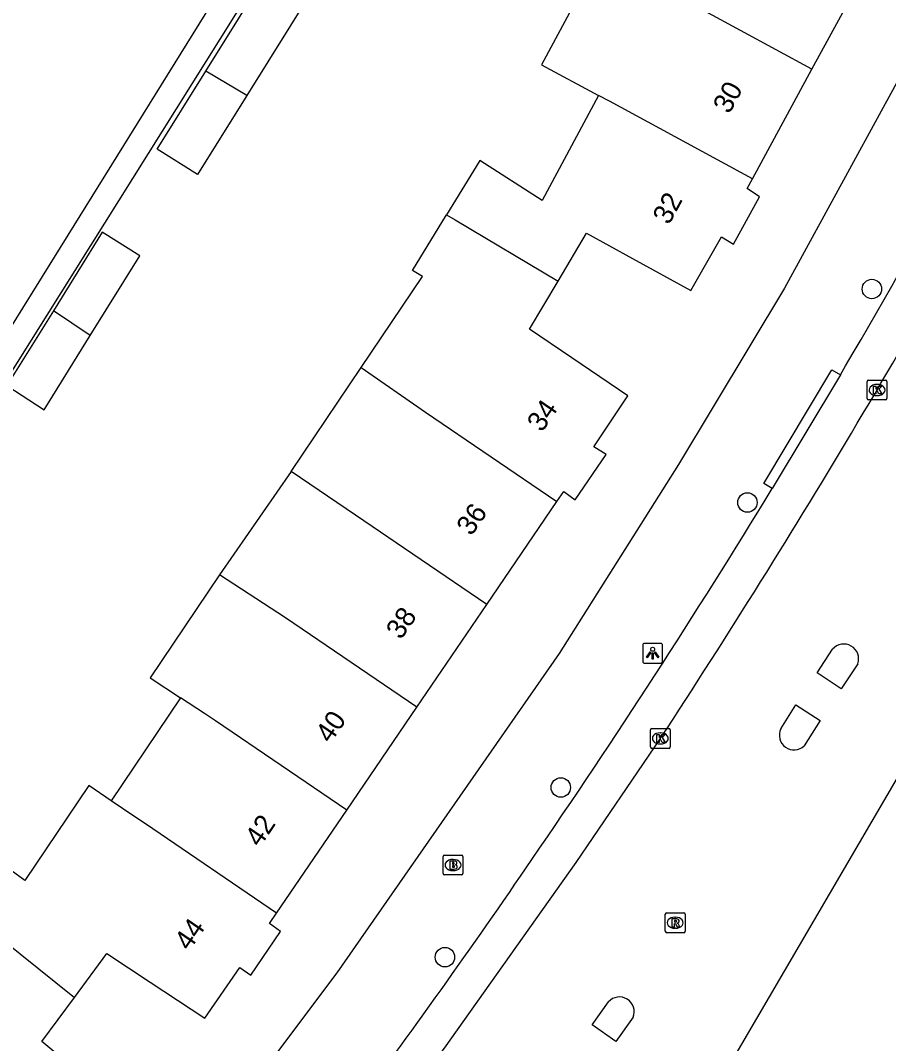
# Model space of a CAD drawing. Extents: x 161771 to 163125, y 382479 to 383177.
# Drawn here: x 162405.3 to 162448.9, y 382626.5 to 382677.9 of the extents above; entities that cross this region are included whole.
import ezdxf

# ---------------------------------------------------------------- set-up
doc = ezdxf.new("R2010")
doc.units = 0
for name, color, linetype in [('IMGEO_Boom', 7, 'Continuous'), ('IMGEO_Brandkraan', 7, 'Continuous'), ('IMGEO_Kolk', 7, 'Continuous'), ('IMGEO_Lichtpunt', 7, 'Continuous'), ('IMGEO_Pand', 7, 'Continuous'), ('IMGEO_Pand_nummerreeks', 7, 'Continuous'), ('IMGEO_Rijbaan_lokaal_open', 7, 'Continuous'), ('IMGEO_Rioolput', 7, 'Continuous'), ('IMGEO_Voetpad_open', 7, 'Continuous')]:
    doc.layers.add(name, color=color, linetype=linetype)

msp = doc.modelspace()

# ---------------------------------------------------------------- linework, layer by layer
at = {"layer": 'IMGEO_Boom'}
for centre in [(162448.106, 382664.408), (162441.847, 382653.678), (162432.46, 382639.354), (162426.633, 382630.828)]:
    msp.add_circle(centre, 0.489, dxfattribs=at)
at = {"layer": 'IMGEO_Brandkraan'}
for p, q in [((162426.539, 382635.032), (162426.539, 382635.884)), ((162426.614, 382635.958), (162427.466, 382635.958)), ((162427.027, 382635.738), (162427.052, 382635.738)), ((162427.54, 382635.884), (162427.54, 382635.032)), ((162427.05, 382635.178), (162427.025, 382635.178)), ((162427.466, 382634.958), (162426.614, 382634.958))]:
    msp.add_line(p, q, dxfattribs=at)
for points in [[(162426.539, 382635.032), (162426.539, 382635.884)], [(162426.614, 382635.958), (162427.466, 382635.958)], [(162426.887, 382635.658), (162426.887, 382635.258), (162427.1, 382635.258)], [(162427.118, 382635.658), (162426.887, 382635.658)], [(162427.066, 382635.577), (162427.012, 382635.577), (162427.012, 382635.501)], [(162427.54, 382635.884), (162427.54, 382635.032)], [(162427.012, 382635.501), (162427.065, 382635.501)], [(162427.074, 382635.425), (162427.012, 382635.425), (162427.012, 382635.344)], [(162427.012, 382635.344), (162427.074, 382635.344)], [(162427.466, 382634.958), (162426.614, 382634.958)]]:
    msp.add_lwpolyline(points, dxfattribs=at)
for centre, radius, start, end in [((162426.616, 382635.882), 0.0765, 91.552, 178.448), ((162426.616, 382635.882), 0.0765, 91.552, 178.448), ((162427.067, 382635.539), 0.0379, 267.8285, 90.9355), ((162427.122, 382635.513), 0.145, 59.4692, 91.5367), ((162427.147, 382635.56), 0.0922, 285.5137, 58.1501), ((162427.464, 382635.882), 0.0765, 1.552, 88.448), ((162427.464, 382635.882), 0.0765, 1.552, 88.448), ((162426.616, 382635.034), 0.0765, 181.552, 268.448), ((162426.616, 382635.034), 0.0765, 181.552, 268.448), ((162427.075, 382635.384), 0.0404, 269.8759, 90.5077), ((162427.106, 382635.509), 0.251, 268.6676, 293.5347), ((162427.152, 382635.368), 0.105, 301.3115, 78.989), ((162427.464, 382635.034), 0.0765, 271.552, 358.448), ((162427.464, 382635.034), 0.0765, 271.552, 358.448)]:
    msp.add_arc(centre, radius, start, end, dxfattribs=at)
for centre, major_axis, ratio, start_param, end_param in [((162427.026, 382635.458), (-0.387, 0.002), 0.722429, 4.712389, 7.853982), ((162427.051, 382635.458), (-0.39, 0.002), 0.717154, 1.570796, 4.712389)]:
    msp.add_ellipse(centre, major_axis=major_axis, ratio=ratio, start_param=start_param, end_param=end_param, dxfattribs=at)
at = {"layer": 'IMGEO_Kolk'}
for p, q in [((162447.865, 382658.908), (162447.865, 382659.76)), ((162447.94, 382659.834), (162448.792, 382659.834)), ((162448.866, 382659.76), (162448.866, 382658.908)), ((162448.353, 382659.614), (162448.378, 382659.614)), ((162448.792, 382658.834), (162447.94, 382658.834)), ((162448.376, 382659.054), (162448.351, 382659.054)), ((162436.966, 382641.395), (162436.966, 382642.247)), ((162437.041, 382642.321), (162437.893, 382642.321)), ((162437.967, 382642.247), (162437.967, 382641.395)), ((162437.454, 382642.101), (162437.479, 382642.101)), ((162437.893, 382641.321), (162437.041, 382641.321)), ((162437.477, 382641.541), (162437.452, 382641.541))]:
    msp.add_line(p, q, dxfattribs=at)
for points in [[(162447.865, 382658.908), (162447.865, 382659.76)], [(162447.94, 382659.834), (162448.792, 382659.834)], [(162448.866, 382659.76), (162448.866, 382658.908)], [(162448.186, 382659.534), (162448.309, 382659.534), (162448.309, 382659.383), (162448.439, 382659.534), (162448.603, 382659.534), (162448.457, 382659.383), (162448.61, 382659.134), (162448.458, 382659.134), (162448.373, 382659.298), (162448.309, 382659.231), (162448.309, 382659.134), (162448.186, 382659.134), (162448.186, 382659.534)], [(162448.792, 382658.834), (162447.94, 382658.834)], [(162436.966, 382641.395), (162436.966, 382642.247)], [(162437.041, 382642.321), (162437.893, 382642.321)], [(162437.967, 382642.247), (162437.967, 382641.395)], [(162437.287, 382642.021), (162437.41, 382642.021), (162437.41, 382641.87), (162437.54, 382642.021), (162437.704, 382642.021), (162437.558, 382641.87), (162437.711, 382641.621), (162437.559, 382641.621), (162437.474, 382641.785), (162437.41, 382641.718), (162437.41, 382641.621), (162437.287, 382641.621), (162437.287, 382642.021)], [(162437.893, 382641.321), (162437.041, 382641.321)]]:
    msp.add_lwpolyline(points, dxfattribs=at)
for centre, start, end in [((162447.942, 382659.758), 91.552, 178.448), ((162447.942, 382659.758), 91.552, 178.448), ((162448.79, 382659.758), 1.552, 88.448), ((162448.79, 382659.758), 1.552, 88.448), ((162447.942, 382658.91), 181.552, 268.448), ((162447.942, 382658.91), 181.552, 268.448), ((162448.79, 382658.91), 271.552, 358.448), ((162448.79, 382658.91), 271.552, 358.448), ((162437.043, 382642.245), 91.552, 178.448), ((162437.043, 382642.245), 91.552, 178.448), ((162437.891, 382642.245), 1.552, 88.448), ((162437.891, 382642.245), 1.552, 88.448), ((162437.043, 382641.397), 181.552, 268.448), ((162437.043, 382641.397), 181.552, 268.448), ((162437.891, 382641.397), 271.552, 358.448), ((162437.891, 382641.397), 271.552, 358.448)]:
    msp.add_arc(centre, 0.0765, start, end, dxfattribs=at)
for centre, major_axis, ratio, start_param, end_param in [((162448.352, 382659.334), (-0.387, 0.002), 0.722429, 4.712389, 7.853982), ((162448.377, 382659.334), (-0.39, 0.002), 0.717154, 1.570796, 4.712389), ((162437.453, 382641.821), (-0.387, 0.002), 0.722429, 4.712389, 7.853982), ((162437.478, 382641.821), (-0.39, 0.002), 0.717154, 1.570796, 4.712389)]:
    msp.add_ellipse(centre, major_axis=major_axis, ratio=ratio, start_param=start_param, end_param=end_param, dxfattribs=at)
at = {"layer": 'IMGEO_Lichtpunt'}
for p, q in [((162436.581, 382646.504), (162436.581, 382645.697)), ((162436.581, 382646.504), (162436.581, 382645.697)), ((162437.483, 382646.599), (162436.675, 382646.599)), ((162437.483, 382646.599), (162436.675, 382646.599)), ((162437.577, 382645.697), (162437.577, 382646.504)), ((162437.577, 382645.697), (162437.577, 382646.504)), ((162436.675, 382645.603), (162437.483, 382645.603)), ((162436.675, 382645.603), (162437.483, 382645.603))]:
    msp.add_line(p, q, dxfattribs=at)
for points in [[(162436.955, 382646.168), (162436.994, 382646.14), (162436.806, 382645.878), (162436.768, 382645.905), (162436.955, 382646.168)], [(162437.057, 382646.12), (162437.104, 382646.12), (162437.104, 382645.798), (162437.057, 382645.798), (162437.057, 382646.12)], [(162437.167, 382646.14), (162437.205, 382646.167), (162437.392, 382645.905), (162437.353, 382645.877), (162437.167, 382646.14)]]:
    msp.add_lwpolyline(points, dxfattribs=at)
msp.add_circle((162437.08, 382646.302), 0.0994, dxfattribs=at)
for centre, start, end in [((162436.675, 382646.504), 90, 180), ((162436.675, 382646.504), 90, 180), ((162437.483, 382646.504), 0, 90), ((162437.483, 382646.504), 0, 90), ((162436.675, 382645.697), 180, 270), ((162436.675, 382645.697), 180, 270), ((162437.483, 382645.697), 270, 0), ((162437.483, 382645.697), 270, 360)]:
    msp.add_arc(centre, 0.0946, start, end, dxfattribs=at)
at = {"layer": 'IMGEO_Pand'}
for points in [[(162395.631, 382648.374), (162395.908, 382648.202), (162415.558, 382679.821), (162419.647, 382686.401)], [(162434.44, 382681.175), (162431.493, 382675.676), (162434.357, 382674.141)], [(162445.09, 382675.453), (162437.903, 382679.362), (162437.319, 382679.668), (162434.44, 382681.175)], [(162445.09, 382675.453), (162448.085, 382680.957)], [(162414.603, 382675.357), (162417.885, 382680.633), (162419.919, 382679.368), (162416.661, 382674.131)], [(162416.661, 382674.131), (162414.195, 382670.168), (162412.162, 382671.433), (162414.603, 382675.357)], [(162416.661, 382674.131), (162414.603, 382675.357)], [(162442.094, 382669.947), (162445.09, 382675.453)], [(162434.357, 382674.141), (162431.521, 382668.851), (162428.383, 382670.869), (162426.712, 382668.136)], [(162442.094, 382669.947), (162434.908, 382673.857), (162434.357, 382674.141)], [(162432.325, 382664.805), (162433.759, 382667.214), (162436.058, 382665.948), (162438.994, 382664.332), (162440.55, 382667.034), (162441.151, 382666.669), (162442.449, 382669.037), (162441.83, 382669.462), (162442.094, 382669.947)], [(162422.423, 382660.462), (162425.507, 382665.032), (162424.997, 382665.333), (162426.712, 382668.136)], [(162426.712, 382668.136), (162427.152, 382667.885), (162432.325, 382664.805)], [(162408.79, 382662.067), (162411.286, 382666.08), (162409.39, 382667.26), (162406.938, 382663.319)], [(162432.261, 382653.724), (162432.607, 382654.231), (162433.176, 382653.806), (162434.742, 382656.098), (162434.122, 382656.473), (162435.835, 382659.041), (162433.015, 382660.954), (162430.891, 382662.395), (162432.325, 382664.805)], [(162406.938, 382663.319), (162404.604, 382659.566), (162406.473, 382658.343), (162408.79, 382662.067)], [(162408.79, 382662.067), (162406.938, 382663.319)], [(162418.896, 382655.236), (162422.423, 382660.462)], [(162422.423, 382660.462), (162425.652, 382658.22), (162432.261, 382653.724)], [(162418.896, 382655.236), (162415.299, 382650.046)], [(162428.738, 382648.554), (162422.133, 382653.048), (162418.896, 382655.236)], [(162428.738, 382648.554), (162432.261, 382653.724)], [(162415.299, 382650.046), (162411.8, 382644.861), (162413.327, 382643.861)], [(162425.214, 382643.385), (162418.613, 382647.876), (162415.299, 382650.046)], [(162425.214, 382643.385), (162428.738, 382648.554)], [(162413.327, 382643.861), (162409.839, 382638.691)], [(162421.691, 382638.215), (162415.094, 382642.704), (162414.533, 382643.072), (162413.327, 382643.861)], [(162421.691, 382638.215), (162425.214, 382643.385)], [(162409.839, 382638.691), (162408.719, 382639.447), (162405.499, 382634.676), (162404.822, 382635.183), (162402.963, 382632.807)], [(162418.168, 382633.046), (162411.575, 382637.532), (162411.033, 382637.885), (162409.839, 382638.691)], [(162418.168, 382633.046), (162421.691, 382638.215)], [(162407.997, 382628.803), (162409.635, 382631.012), (162411.812, 382629.572), (162414.551, 382627.759), (162416.324, 382630.315), (162416.874, 382629.921), (162418.357, 382632.114), (162417.808, 382632.518), (162418.168, 382633.046)], [(162402.963, 382632.807), (162403.454, 382632.444), (162407.997, 382628.803)], [(162406.871, 382617.818), (162407.293, 382618.33), (162407.849, 382617.796), (162409.532, 382619.984), (162408.993, 382620.427), (162410.931, 382622.789), (162408.349, 382624.937), (162406.358, 382626.593), (162407.997, 382628.803)]]:
    msp.add_lwpolyline(points, dxfattribs=at)
at = {"layer": 'IMGEO_Rijbaan_lokaal_open'}
for points in [[(162447.397, 382645.571), (162446.564, 382644.314), (162445.349, 382645.12), (162446.132, 382646.301)], [(162443.522, 382642.305), (162444.277, 382643.505), (162445.511, 382642.729)], [(162445.511, 382642.729), (162444.708, 382641.452)], [(162437.466, 382641.817), (162433.213, 382635.583), (162426.587, 382626.258), (162423.207, 382621.752), (162416.618, 382612.746), (162409.905, 382604.413), (162406.248, 382600.285)], [(162439.892, 382623.551), (162440.057, 382623.883), (162450.381, 382641.534), (162450.597, 382641.828)], [(162436.1, 382627.81), (162435.223, 382626.583), (162434.037, 382627.431), (162434.861, 382628.584)]]:
    msp.add_lwpolyline(points, dxfattribs=at)
for centre, radius, start, end in [((162074.96, 382879.557), 433.51, 326.74218, 331.68168), ((162446.698, 382645.821), 0.742, 340.2896, 139.7341), ((162444.193, 382641.987), 0.743, 154.6189, 313.9318), ((162435.41, 382628.084), 0.742, 338.3406, 137.6736)]:
    msp.add_arc(centre, radius, start, end, dxfattribs=at)
at = {"layer": 'IMGEO_Rioolput'}
for p, q in [((162437.715, 382632.132), (162437.715, 382632.984)), ((162437.79, 382633.058), (162438.642, 382633.058)), ((162438.716, 382632.984), (162438.716, 382632.132)), ((162438.203, 382632.838), (162438.228, 382632.838)), ((162438.642, 382632.058), (162437.79, 382632.058)), ((162438.226, 382632.278), (162438.201, 382632.278))]:
    msp.add_line(p, q, dxfattribs=at)
for points in [[(162437.715, 382632.132), (162437.715, 382632.984)], [(162437.79, 382633.058), (162438.642, 382633.058)], [(162438.716, 382632.984), (162438.716, 382632.132)], [(162438.304, 382632.756), (162438.052, 382632.758), (162438.052, 382632.358)], [(162438.052, 382632.358), (162438.176, 382632.358), (162438.176, 382632.52), (162438.187, 382632.52)], [(162438.23, 382632.677), (162438.176, 382632.677), (162438.176, 382632.596)], [(162438.176, 382632.596), (162438.228, 382632.596)], [(162438.234, 382632.491), (162438.305, 382632.358), (162438.445, 382632.358), (162438.38, 382632.484)], [(162438.642, 382632.058), (162437.79, 382632.058)]]:
    msp.add_lwpolyline(points, dxfattribs=at)
for centre, radius, start, end in [((162437.792, 382632.982), 0.0765, 91.552, 178.448), ((162437.792, 382632.982), 0.0765, 91.552, 178.448), ((162438.64, 382632.982), 0.0765, 1.552, 88.448), ((162438.64, 382632.982), 0.0765, 1.552, 88.448), ((162438.186, 382632.467), 0.0533, 26.0293, 88.6989), ((162438.212, 382632.785), 0.19, 274.7715, 282.9687), ((162438.236, 382632.581), 0.0964, 77.0061, 93.1865), ((162438.25, 382632.638), 0.0378, 276.6634, 79.6772), ((162438.303, 382632.646), 0.109, 350.3612, 89.416), ((162438.301, 382632.646), 0.112, 277.5842, 350.9817), ((162438.285, 382632.431), 0.108, 29.5134, 73.7905), ((162437.792, 382632.134), 0.0765, 181.552, 268.448), ((162437.792, 382632.134), 0.0765, 181.552, 268.448), ((162438.64, 382632.134), 0.0765, 271.552, 358.448), ((162438.64, 382632.134), 0.0765, 271.552, 358.448)]:
    msp.add_arc(centre, radius, start, end, dxfattribs=at)
for centre, major_axis, ratio, start_param, end_param in [((162438.202, 382632.558), (-0.387, 0.002), 0.722429, 4.712389, 7.853982), ((162438.227, 382632.558), (-0.39, 0.002), 0.717154, 1.570796, 4.712389)]:
    msp.add_ellipse(centre, major_axis=major_axis, ratio=ratio, start_param=start_param, end_param=end_param, dxfattribs=at)
at = {"layer": 'IMGEO_Voetpad_open'}
for points in [[(162481.155, 382756.282), (162479.277, 382750), (162475.552, 382737.539), (162469.715, 382720.652), (162462.007, 382700.842), (162457.539, 382690.752), (162451.64, 382678.977), (162443.703, 382664.454), (162438.387, 382655.596), (162432.385, 382646.085), (162421.193, 382630.033), (162412.885, 382618.959), (162400.55, 382603.937), (162397.717, 382600.824)], [(162394.693, 382644.6), (162400.026, 382652.594), (162419.717, 382683.993)], [(162443.099, 382654.384), (162442.668, 382654.635), (162446.089, 382660.344), (162446.52, 382660.093)], [(162446.52, 382660.093), (162446.783, 382660.54)], [(162446.52, 382660.093), (162443.099, 382654.384)]]:
    msp.add_lwpolyline(points, dxfattribs=at)
for centre, radius, start, end in [((162116.582, 382854.367), 382.886, 329.58715, 333.2852), ((162095.693, 382866.449), 407.016, 325.46872, 328.59913), ((162129.235, 382841.437), 365.209, 323.21535, 325.71848)]:
    msp.add_arc(centre, radius, start, end, dxfattribs=at)

# ---------------------------------------------------------------- texts
at = {"layer": 'IMGEO_Pand_nummerreeks'}
for s, rotation, p in [('30', 61.444, (162440.935, 382673.169)), ('32', 61.4416, (162437.901, 382667.593)), ('34', 55.769, (162431.513, 382657.169)), ('36', 55.769, (162427.965, 382651.955)), ('38', 55.769, (162424.42, 382646.743)), ('40', 55.7717, (162420.874, 382641.53)), ('42', 55.7717, (162417.322, 382636.311)), ('44', 55.7717, (162413.777, 382631.1))]:
    msp.add_text(s, height=1, rotation=rotation, dxfattribs=at).set_placement(p)

doc.saveas('drawing.dxf')
